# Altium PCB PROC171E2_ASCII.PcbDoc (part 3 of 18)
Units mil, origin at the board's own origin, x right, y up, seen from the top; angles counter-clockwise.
Board outline 7700 x 2300 mil, 6 copper layers (Top Layer, GND 1, SIG 1, SIG 2, GND 2, Bottom Layer), stack 61.062 mil thick; 938 components, 688 nets, 11933 pads, 1723 vias.
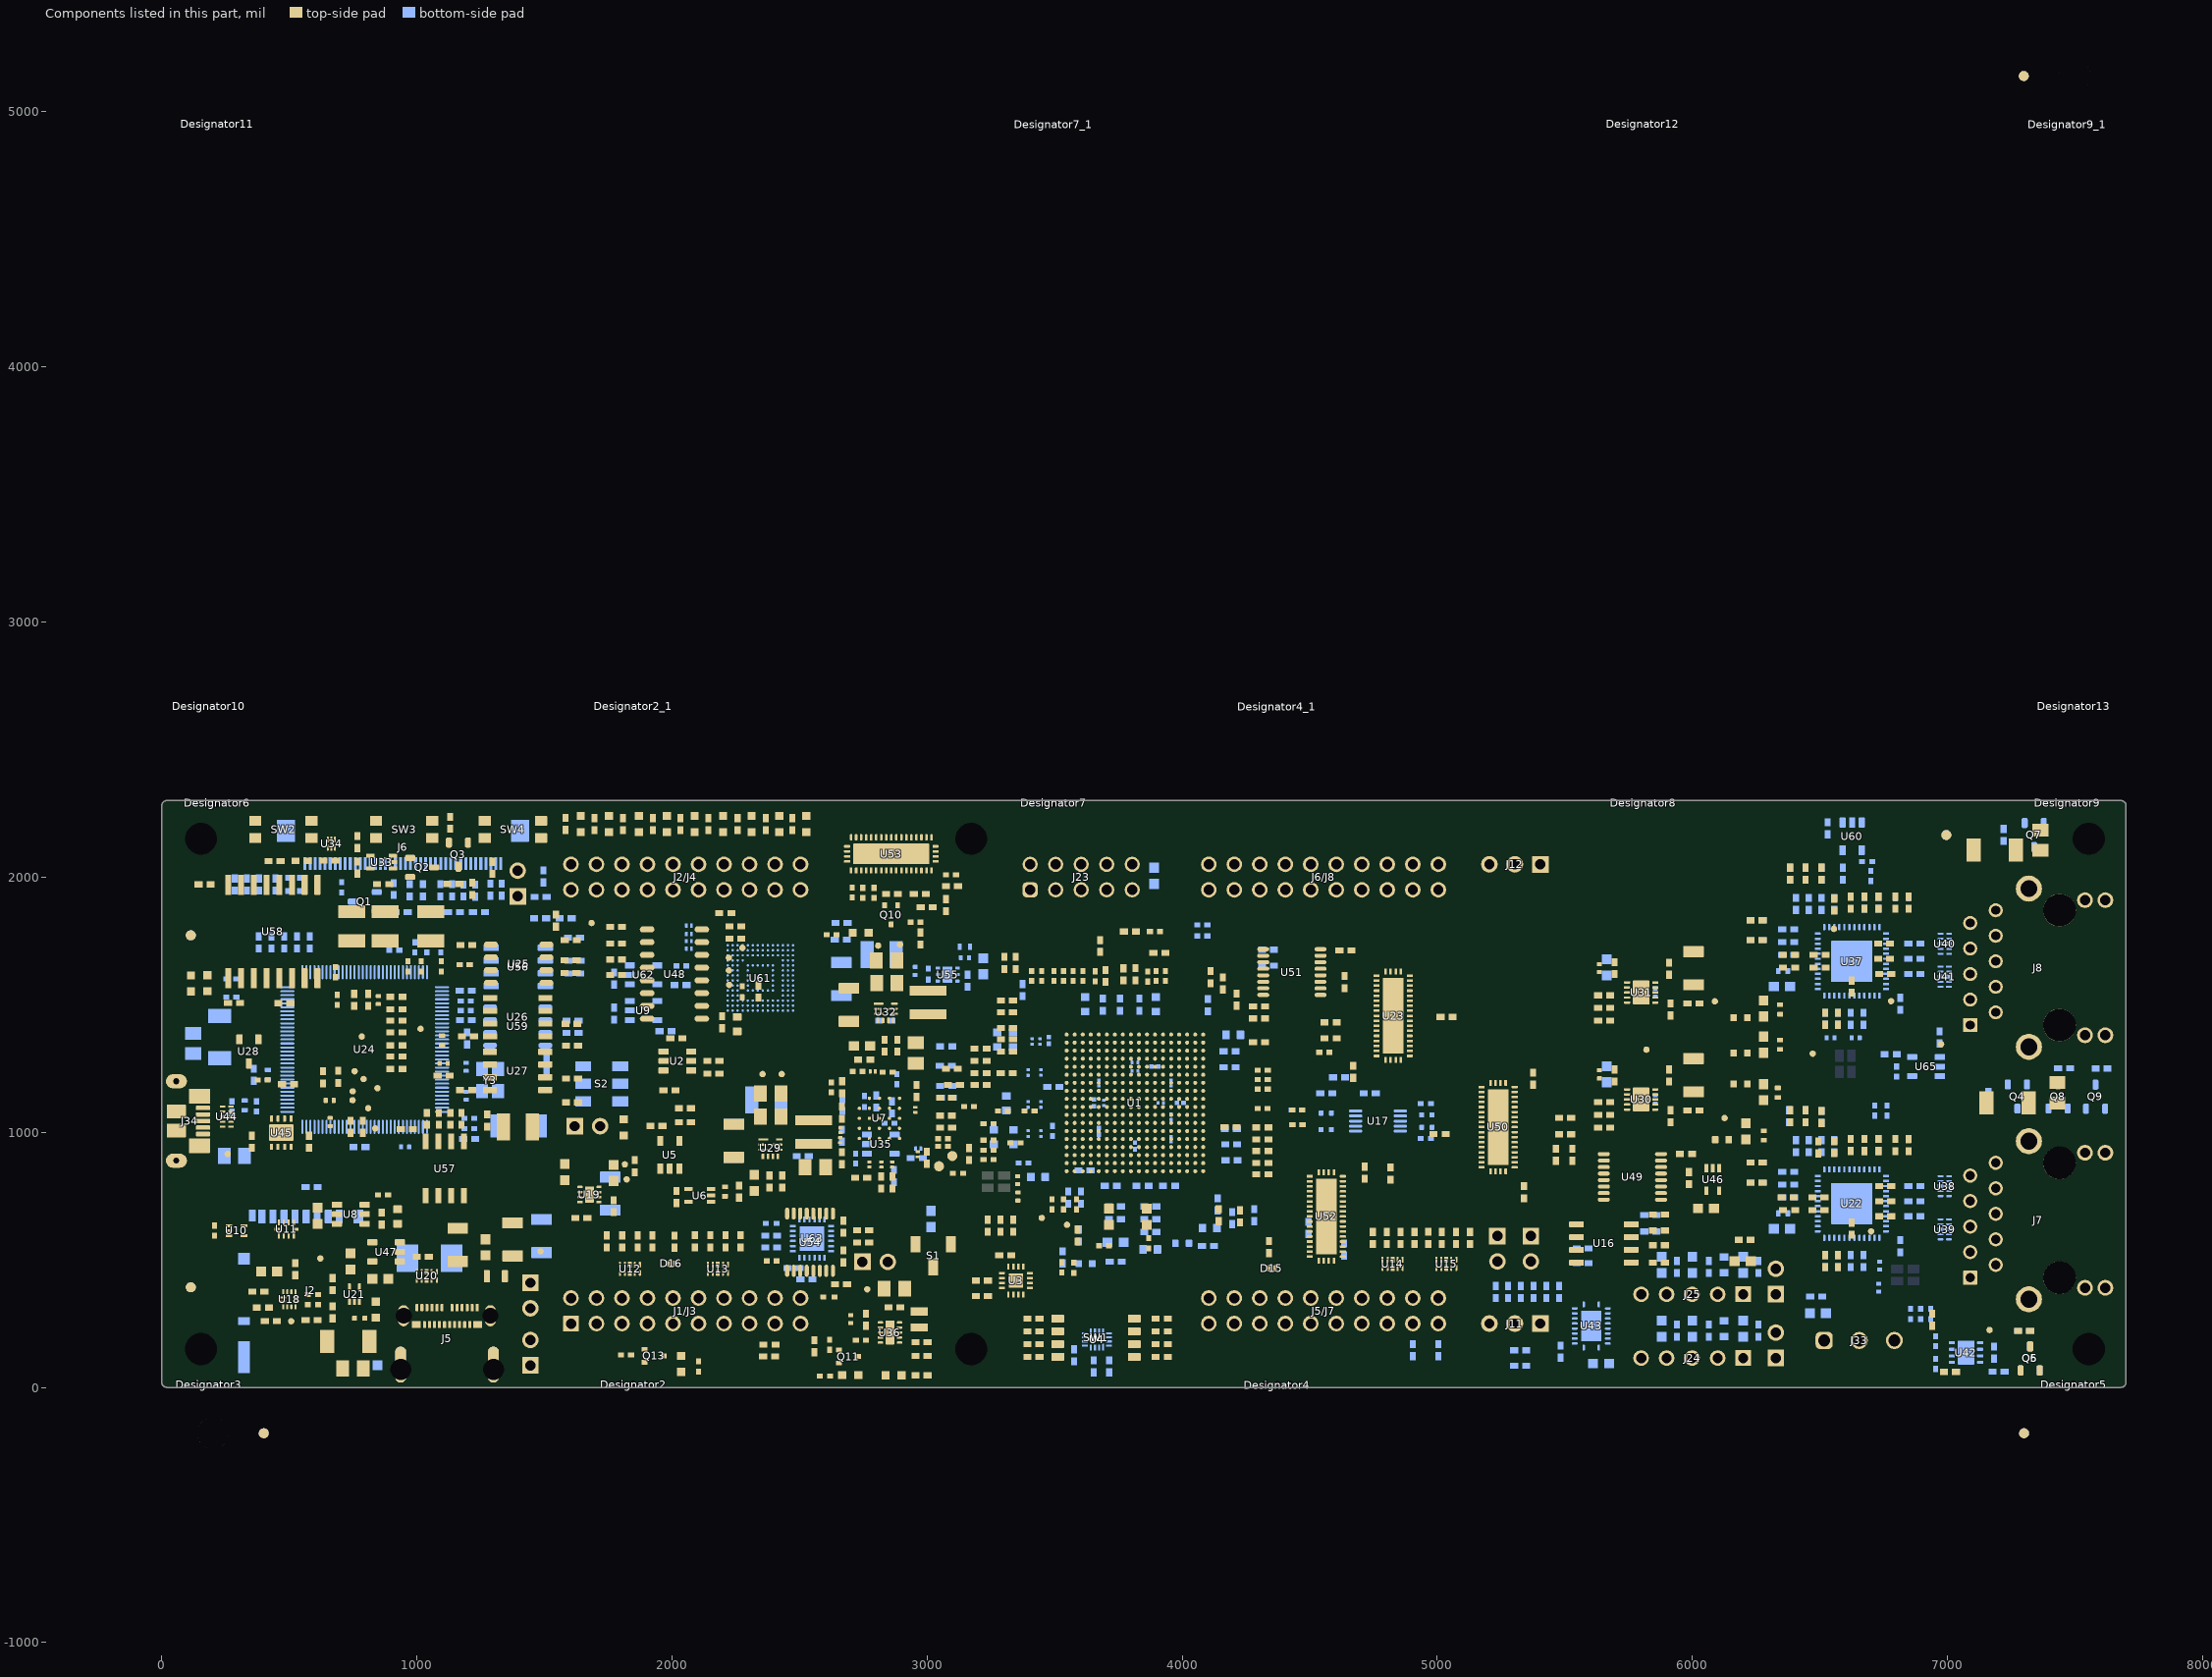
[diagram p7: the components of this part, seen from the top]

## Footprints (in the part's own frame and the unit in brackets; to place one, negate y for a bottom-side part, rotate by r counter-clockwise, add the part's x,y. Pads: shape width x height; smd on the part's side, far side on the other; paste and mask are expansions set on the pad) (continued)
BoosterPack_40pin_J1J3 [mm] "Receptacle, 2.54mm, 10x2, TH"
  rrect6% 1.55x1.55 hole 1.02: 1(1.27,11.43)
  round 1.55 hole 1.02: 2(1.27,8.89) 3(1.27,6.35) 4(1.27,3.81) 5(1.27,1.27) 6(1.27,-1.27) 7(1.27,-3.81) 8(1.27,-6.35) 9(1.27,-8.89) 10(1.27,-11.43) 21(-1.27,11.43) 22(-1.27,8.89) 23(-1.27,6.35) 24(-1.27,3.81) 25(-1.27,1.27) 26(-1.27,-1.27) 27(-1.27,-3.81) 28(-1.27,-6.35) 29(-1.27,-8.89) 30(-1.27,-11.43)
  silkscreen extent -7.62,-12.95 7.62,12.95
BoosterPack_40pin_J2J4 [mm] "Receptacle, 2.54mm, 10x2, TH"
  round 1.55 hole 1.02: 11(-1.27,-11.43) 12(-1.27,-8.89) 13(-1.27,-6.35) 14(-1.27,-3.81) 15(-1.27,-1.27) 16(-1.27,1.27) 17(-1.27,3.81) 18(-1.27,6.35) 19(-1.27,8.89) 20(-1.27,11.43) 31(1.27,-11.43) 32(1.27,-8.89) 33(1.27,-6.35) 34(1.27,-3.81) 35(1.27,-1.27) 36(1.27,1.27) 37(1.27,3.81) 38(1.27,6.35) 39(1.27,8.89) 40(1.27,11.43)
  silkscreen extent -7.62,-12.95 2.48,12.95
BoosterPack_40pin_J5J7 [mm] "Receptacle, 2.54mm, 10x2, TH"
  round 1.55 hole 1.02: 41(1.27,11.43) 42(1.27,8.89) 43(1.27,6.35) 44(1.27,3.81) 45(1.27,1.27) 46(1.27,-1.27) 47(1.27,-3.81) 48(1.27,-6.35) 49(1.27,-8.89) 50(1.27,-11.43) 61(-1.27,11.43) 62(-1.27,8.89) 63(-1.27,6.35) 64(-1.27,3.81) 65(-1.27,1.27) 66(-1.27,-1.27) 67(-1.27,-3.81) 68(-1.27,-6.35) 69(-1.27,-8.89) 70(-1.27,-11.43)
  silkscreen extent -2.48,-12.95 7.62,12.95
BoosterPack_40pin_J6J8 [mm] "Receptacle, 2.54mm, 10x2, TH"
  round 1.55 hole 1.02: 51(-1.27,-11.43) 52(-1.27,-8.89) 53(-1.27,-6.35) 54(-1.27,-3.81) 55(-1.27,-1.27) 56(-1.27,1.27) 57(-1.27,3.81) 58(-1.27,6.35) 59(-1.27,8.89) 60(-1.27,11.43) 71(1.27,-11.43) 72(1.27,-8.89) 73(1.27,-6.35) 74(1.27,-3.81) 75(1.27,-1.27) 76(1.27,1.27) 77(1.27,3.81) 78(1.27,6.35) 79(1.27,8.89) 80(1.27,11.43)
  silkscreen extent -7.62,-12.95 2.48,12.95
BRAKE_WAY_HOLES1X3 [mil]
  round 27 hole 32 unplated mask+0: ""(-50,49.37) ""(0,49.37) ""(50,49.37)
CE_Mark_5mm [mil] "Minimum text height for CE Mark"
D0008A-MFG [mm]
  rrect17% 1.55x0.6 smd paste+0 mask+0: 1(-2.7,1.905) 2(-2.7,0.635) 3(-2.7,-0.635) 4(-2.7,-1.905) 5(2.7,-1.905) 6(2.7,-0.635) 7(2.7,0.635) 8(2.7,1.905)
  silkscreen extent -4.17,-2.5 1.5,2.5
D0008B_HV [mm] "SOIC, 8-Leads, Body 4.9x3.9mm, Pitch 1.27mm, HV / Isolation option"
  rrect17% 1.4x0.6 smd: 1(-2.75,1.905) 2(-2.75,0.635) 3(-2.75,-0.635) 4(-2.75,-1.905) 5(2.75,-1.905) 6(2.75,-0.635) 7(2.75,0.635) 8(2.75,1.905)
  silkscreen extent -3.3,-2.5 0.9,2.5
D0008B_N [mil] "SOIC, 8-Leads, Body 4.9x3.9mm, Pitch 1.27mm, IPC Medium Density"
  oval 55x23.62 smd: 1(-108.5,75) 2(-108.5,25) 3(-108.5,-25) 4(-108.5,-75) 5(108.5,-75) 6(108.5,-25) 7(108.5,25) 8(108.5,75)
  silkscreen extent -130,-98 35,98
D0016A_N [mm] "SOIC, 16-Leads, Body 9.9x3.9mm, Pitch 1.27mm, IPC Medium Density"
  oval 1.45x0.6 smd: 1(-2.725,4.445) 2(-2.725,3.175) 3(-2.725,1.905) 4(-2.725,0.635) 5(-2.725,-0.635) 6(-2.725,-1.905) 7(-2.725,-3.175) 8(-2.725,-4.445) 9(2.725,-4.445) 10(2.725,-3.175) 11(2.725,-1.905) 12(2.725,-0.635) 13(2.725,0.635) 14(2.725,1.905) 15(2.725,3.175) 16(2.725,4.445)
  silkscreen extent -3.3,-5 0.9,5
DBV0005A_N [mm] "SOT23, 5-Leads, Body 2.9x1.6mm, Pitch 0.95mm, Lead Span 2.8mm, IPC Medium Density"
  rrect17% 1x0.6 smd: 1(-1.375,0.95) 2(-1.375,0) 3(-1.375,-0.95) 4(1.375,-0.95) 5(1.375,0.95)
  silkscreen extent -0.25,-1.55 0.25,1.55
DBV0006A_N [mm] "SOT23, 6-Leads, Body 2.9x1.6mm, Pitch 0.95mm, Lead Span 2.8mm, IPC Medium Density"
  rrect17% 1x0.6 smd: 1(-1.375,0.95) 2(-1.375,0) 3(-1.375,-0.95) 4(1.375,-0.95) 5(1.375,0) 6(1.375,0.95)
  silkscreen extent -1.68,-1.55 0.5,1.55
DBZ0003A_N [mm] "SOT23, 3-Leads, Body 2.9x1.3mm, Pitch 0.95mm, Lead Span 2.4mm, IPC Medium Density"
  rrect17% 1x0.6 smd: 1(-1.2,0.95) 2(-1.2,-0.95) 3(1.2,0)
  silkscreen extent 0.2,-1.5 0.7,1.5
DCK0005A_N [mm] "SOT353, 5-Leads, Body 2x1.3mm, Pitch 0.65mm, Lead Span 2.1mm, IPC Medium Density"
  rrect25% 0.85x0.4 smd: 1(-1.125,0.65) 2(-1.125,0) 3(-1.125,-0.65) 4(1.125,-0.65) 5(1.125,0.65)
  silkscreen extent -1.48,-1.02 0.55,1.1
DGS0010A_N [mm] "TSSOP, 10-Leads, Body 3x3mm, Pitch 0.5mm, IPC Medium Density"
  oval 1.35x0.3 smd: 1(-2.225,1) 2(-2.225,0.5) 3(-2.225,0) 4(-2.225,-0.5) 5(-2.225,-1) 6(2.225,-1) 7(2.225,-0.5) 8(2.225,0) 9(2.225,0.5) 10(2.225,1)
  silkscreen extent -2.75,-1.55 0.9,1.55
DPY0002A [mm] "X1SON-2"
  rrect57% 0.35x0.6 smd paste-0.5 mask+0: 1(-0.325,0) 2(0.325,0)
  rrect50% 0.3x0.5 on Top Paste: 1S(-0.35,0) 2S(0.35,0)
  silkscreen extent -0.85,-0.02 -0.8,0.02
DQA0010A#1 [mm] "SON, 10-Leads, Body 1x2.5mm, Pitch 0.5mm, TI Recommended"
  rrect50% 0.565x0.2 smd: 1(-0.417,1) 2(-0.417,0.5) 4(-0.417,-0.5) 5(-0.417,-1) 6(0.417,-1) 7(0.417,-0.5) 9(0.417,0.5) 10(0.417,1)
  rrect28% 0.565x0.36 on Top Paste: 3(-0.417,0) 8(0.417,0)
  rrect25% 0.565x0.4 smd paste-0.2: 3(-0.417,0) 8(0.417,0)
  silkscreen extent -0.67,-1.45 0.55,1.45
DQA0010A#2 [mm] "SON, 10-Leads, Body 1x2.5mm, Pitch 0.5mm, TI Recommended"
  rrect50% 0.565x0.2 smd: 1(-0.417,1) 2(-0.417,0.5) 4(-0.417,-0.5) 5(-0.417,-1) 6(0.417,-1) 7(0.417,-0.5) 9(0.417,0.5) 10(0.417,1)
  rrect28% 0.565x0.36 on Bottom Paste: 3(-0.417,0) 8(0.417,0)
  rrect25% 0.565x0.4 smd paste-0.2: 3(-0.417,0) 8(0.417,0)
  silkscreen extent -0.67,-1.45 0.55,1.45
DQC0010A [mm] "SON, 10-Leads, Body 2x3mm, Pitch 0.5mm, Thermal Pad 2.4x0.84mm"
  rrect40% 0.5x0.25 smd: 1(-0.95,1) 2(-0.95,0.5) 3(-0.95,0) 4(-0.95,-0.5) 5(-0.95,-1) 6(0.95,-1) 7(0.95,-0.5) 8(0.95,0) 9(0.95,0.5) 10(0.95,1)
  rrect12% 0.8x1.08 on Top Paste: 11(0,-0.64) 11(0,0.64)
  rrect12% 0.84x2.4 smd paste-0.42: 11(0,0)
  silkscreen extent -1.18,-1.68 1.17,1.68
DRB0008B [mm] "SON, 8-Leads, Body 3x3mm, Pitch 0.65mm, Thermal Pad 2.4x1.65mm, TI Recommended"
  rrect33% 0.6x0.3 smd: 1(-1.4,0.975) 2(-1.4,0.325) 3(-1.4,-0.325) 4(-1.4,-0.975) 5(1.4,-0.975) 6(1.4,-0.325) 7(1.4,0.325) 8(1.4,0.975)
  rrect50% 1.47x1.06 on Top Paste: 9(0,0.63) 9(0,-0.63)
  rrect6% 1.65x2.4 smd paste-1.2: 9(0,0)
  silkscreen extent -1.73,-1.73 1.73,1.73
DRB0008J [mm] "VSON-8"
  rrect33% 0.6x0.31 smd: 1(-1.4,0.975) 2(-1.4,0.325) 3(-1.4,-0.325) 4(-1.4,-0.975) 5(1.4,-0.975) 6(1.4,-0.325) 7(1.4,0.325) 8(1.4,0.975)
  rrect6% 1.65x2.4 smd paste-1.2: 9(0,0)
  silkscreen extent -1.73,-1.73 1.73,1.73
DRC0010J [mm] "VSON-10"
  rrect42% 0.6x0.24 smd: 1(-1.4,1) 2(-1.4,0.5) 3(-1.4,0) 4(-1.4,-0.5) 5(-1.4,-1) 6(1.4,-1) 7(1.4,-0.5) 8(1.4,0) 9(1.4,0.5) 10(1.4,1)
  rrect12% 1.65x2.4 smd paste-1 mask+0: 11(0,0)
DRL0005A [mm] "SOTFL, 5-Flat Leads, Body 1.2x1.6x0.6mm, Pitch 0.5mm, TI recommended"
  rrect33% 0.67x0.3 smd: 1(-0.74,0.5) 2(-0.74,0) 3(-0.74,-0.5) 4(0.74,-0.5) 5(0.74,0.5)
  silkscreen extent -0.9,-0.95 0.5,0.95
DRV0006A [mm] "SON, 6-Leads, Body 2x2mm, Pitch 0.65mm, Thermal Pad 1.6x1mm, TI Recommended"
  rrect33% 0.45x0.3 smd: 1(-0.975,0.65) 2(-0.975,0) 3(-0.975,-0.65) 4(0.975,-0.65) 5(0.975,0) 6(0.975,0.65)
  rrect14% 1x0.7 on Bottom Paste: 7(0,-0.45) 7(0,0.45)
  rrect10% 1x1.6 smd paste-0.5: 7(0,0)
  silkscreen extent -1.05,-1.2 1.05,1.2
DSF0006A [mm] "TI recommended land pattern"
  rrect59% 0.6x0.17 smd mask+0: 1(-0.4,0.35) 2(-0.4,0) 3(-0.4,-0.35) 4(0.4,-0.35) 5(0.4,0) 6(0.4,0.35)
  silkscreen extent -0.6,-0.63 0.6,0.63
DSG0008B [mm] "SON, 8-Leads, Body 2x2mm, Pitch 0.5mm, Thermal Pad 1.6x0.9mm, TI Recommended"
  rrect14% 0.9x0.7 on Top Paste: 0(0,-0.45) 0(0,0.45)
  rrect40% 0.5x0.25 smd: 1(-0.95,0.75) 2(-0.95,0.25) 3(-0.95,-0.25) 4(-0.95,-0.75) 5(0.95,-0.75) 6(0.95,-0.25) 7(0.95,0.25) 8(0.95,0.75)
  rrect11% 0.9x1.6 smd paste-0.45: 9(0,0)
  silkscreen extent -1.07,-1.15 1.07,1.15
DW0016A-MFG [mm]
  rrect17% 2x0.6 smd paste+0 mask+0: 1(-4.65,4.445) 2(-4.65,3.175) 3(-4.65,1.905) 4(-4.65,0.635) 5(-4.65,-0.635) 6(-4.65,-1.905) 7(-4.65,-3.175) 8(-4.65,-4.445) 9(4.65,-4.445) 10(4.65,-3.175) 11(4.65,-1.905) 12(4.65,-0.635) 13(4.65,0.635) 14(4.65,1.905) 15(4.65,3.175) 16(4.65,4.445)
  silkscreen extent -6.32,-5.25 3.15,5.25
FCC_disclaimer [mil]
Fiducial10-20 [mm]
  round 1 smd mask+0: 1(0,0)
  Top Layer keep-out circle w1.178: c0,0 r0.5
FP-2012670005_CONN_USB_9MM39_8MM21-MFG [mm]
  rrect100% 1.1x2.1 hole 1.6 slot 0.6 at 0 deg paste-1000 mask+0: 1(-4.32,3.205) 2(4.32,3.205)
  rrect100% 0.6x2.1 hole 2.1 slot 0.6 at 0 deg paste-1000 mask+0: 3(-4.62,-2.155) 4(4.62,-2.155)
  rrect100% 1.1x3.6 smd paste-1000 mask+0: 3(-4.62,-1.655) 4(4.62,-1.655)
  rrect100% 1.1x3.6 smd far side paste-1000 mask+0: 3(-4.62,-1.655) 4(4.62,-1.655)
  rrect33% 0.3x0.7 smd paste+0 mask+0: A1(-3,4.015) A2(-2.5,4.015) A3(-2,4.015) A4(-1.5,4.015) A5(-1,4.015) A6(-0.5,4.015) A7(0.5,4.015) A8(1,4.015) A9(1.5,4.015) A10(2,4.015) A11(2.5,4.015) A12(3,4.015) B2(2.25,2.315) B3(1.75,2.315) B4(1.25,2.315) B5(0.75,2.315) B6(0.25,2.315) B7(-0.25,2.315) B8(-0.75,2.315) B9(-1.25,2.315) B10(-1.75,2.315) B11(-2.25,2.315)
  rrect14% 0.9x0.7 smd paste+0 mask+0: B1(3.05,2.315) B12(-3.05,2.315)
  silkscreen extent -4.77,0.52 4.77,5.03
FP-74405020100_SMT_IND_2MM0_1MM6-MFG [mm]
  rect 0.8x1.7 smd paste+0 mask+0: 1(-0.8,0) 2(0.8,0)
FP-416131160804_SMT_SW-MFG [mm]
  rrect13% 0.76x1.27 smd paste+0 mask+0: 1(-1.905,-3.81) 2(-0.635,-3.81) 3(0.635,-3.81) 4(1.905,-3.81) 5(1.905,3.81) 6(0.635,3.81) 7(-0.635,3.81) 8(-1.905,3.81)
  silkscreen extent -3.27,-4.12 3.27,2.93
FP-434351045816_SMT_SW_4MM7_4MM5-MFG [mm]
  rrect10% 1.2x1 smd paste+0 mask+0: 1(2.8,0.85) 2(2.8,-0.85) 3(-2.8,0.85) 4(-2.8,-0.85)
  silkscreen extent -2.4,0.73 4.07,1.85
FP-BLM18EG121SN1D_0603-MFG [mm]
  rrect15% 0.65x0.7 smd paste+0 mask+0: 1(-0.675,0) 2(0.675,0)
  silkscreen extent -0.87,-0.8 0.87,0.8
FP-BLM21PG300SN1D_0805-MFG [mm]
  rrect17% 0.6x1.2 smd paste-1000 mask+0: 1(-0.9,0) 2(0.9,0)
  silkscreen extent -0.23,-0.72 0.23,0.72
FP-CL10A335KP8NNNC_0603-MFG [mm]
  rrect13% 0.76x0.85 smd paste+0 mask+0: 1(-0.72,0) 2(0.72,0)
  silkscreen extent -0.85,-0.8 0.85,0.8
"FP-CRCW020122R0FNED_0201 (0603 metric)-MFG" [mm]
  rrect36% 0.28x0.43 smd paste+0 mask+0: 1(-0.255,0) 2(0.255,0)
FP-ERA-2APB621X_0402-MFG [mm]
  rrect21% 0.475x0.5 smd paste+0 mask+0: 1(-0.512,0) 2(0.512,0)
  silkscreen extent -0.5,-0.63 0.5,0.63
FP-ERJ-2GEJ152X_0402-MFG [mm]
  rrect21% 0.475x0.5 smd paste+0 mask+0: 1(-0.512,0) 2(0.513,0)
  silkscreen extent -0.53,-0.63 0.53,0.63
FP-FH12A-40S-0.5SH(55)_FFC40-MFG [mm]
  rrect33% 0.3x1.3 smd paste-1000 mask+0: 1(9.75,-3.725) 2(9.25,-3.725) 3(8.75,-3.725) 4(8.25,-3.725) 5(7.75,-3.725) 6(7.25,-3.725) 7(6.75,-3.725) 8(6.25,-3.725) 9(5.75,-3.725) 10(5.25,-3.725) 11(4.75,-3.725) 12(4.25,-3.725) 13(3.75,-3.725) 14(3.25,-3.725) 15(2.75,-3.725) 16(2.25,-3.725) 17(1.75,-3.725) 18(1.25,-3.725) 19(0.75,-3.725) 20(0.25,-3.725) 21(-0.25,-3.725) 22(-0.75,-3.725) 23(-1.25,-3.725) 24(-1.75,-3.725) 25(-2.25,-3.725) 26(-2.75,-3.725) 27(-3.25,-3.725) 28(-3.75,-3.725) 29(-4.25,-3.725) 30(-4.75,-3.725) 31(-5.25,-3.725) 32(-5.75,-3.725) 33(-6.25,-3.725) 34(-6.75,-3.725) 35(-7.25,-3.725) 36(-7.75,-3.725) 37(-8.25,-3.725) 38(-8.75,-3.725) 39(-9.25,-3.725) 40(-9.75,-3.725)
  rrect6% 1.8x2.2 smd paste+0 mask+0: 41(-11.65,-0.475) 42(11.65,-0.475)
  silkscreen extent -12.35,-4.32 12.35,3.2
FP-GCM155R72A272KA37D_0402-MFG [mm]
  rrect25% 0.4x0.5 smd paste+0 mask+0: 1(-0.4,0) 2(0.4,0)
  silkscreen extent -0.53,-0.65 0.53,0.65
FP-GJM1555C1H8R0DB01D_0402-MFG [mm]
  rrect25% 0.4x0.5 smd paste+0 mask+0: 1(-0.4,0) 2(0.4,0)
  silkscreen extent -0.53,-0.63 0.53,0.63
FP-GJM1555C1H120JB01D_0402-MFG [mm]
  rrect25% 0.4x0.5 smd paste+0 mask+0: 1(-0.4,0) 2(0.4,0)
  silkscreen extent -0.53,-0.63 0.53,0.63
FP-GJM1555C1H150FB01D_0402-MFG [mm]
  rrect25% 0.4x0.5 smd paste+0 mask+0: 1(-0.4,0) 2(0.4,0)
  silkscreen extent -0.53,-0.63 0.53,0.63
FP-GQM1875C2E101JB12D_0603-MFG [mm]
  rrect13% 0.75x0.9 smd paste+0 mask+0: 1(-0.775,0) 2(0.775,0)
  silkscreen extent -1,-0.67 1,0.67
FP-GRM32EC72A106KE05L_1210-MFG [mm]
  rrect9% 1.1x2.05 smd paste+0 mask+0: 1(-1.65,0) 2(1.65,0)
  silkscreen extent -0.72,-1.35 0.72,1.35
FP-GRM033C80J105ME05D_0201-MFG [mm]
  rrect33% 0.3x0.35 smd paste+0 mask+0: 1(-0.282,0) 2(0.282,0)
  silkscreen extent -0.35,-0.58 0.35,0.58
FP-GRM155C71A105KE11D_0402-MFG [mm]
  rrect25% 0.4x0.5 smd paste+0 mask+0: 1(-0.4,0) 2(0.4,0)
  silkscreen extent -0.55,-0.65 0.55,0.65
FP-GRM155R71H104KE14D_0402-MFG [mm]
  rrect25% 0.4x0.5 smd paste+0 mask+0: 1(-0.4,0) 2(0.4,0)
  silkscreen extent -0.5,-0.65 0.5,0.65
FP-GRM1555C1E103JE01D_0402-MFG [mm]
  rrect22% 0.45x0.6 smd paste+0 mask+0: 1(-0.475,0) 2(0.475,0)
  silkscreen extent -0.58,-0.73 0.58,0.72
FP-IS25LX256-LHLE_TFBGA24-IPC_C [mm]
  round 0.34 smd paste+0 mask+0: A2(-1,2) A3(0,2) A4(1,2) A5(2,2) B1(-2,1) B2(-1,1) B3(0,1) B4(1,1) B5(2,1) C1(-2,0) C2(-1,0) C3(0,0) C4(1,0) C5(2,0) D1(-2,-1) D2(-1,-1) D3(0,-1) D4(1,-1) D5(2,-1) E1(-2,-2) E2(-1,-2) E3(0,-2) E4(1,-2) E5(2,-2)
  silkscreen extent -3.62,-4 3,4
FP-KGM05CR51A106MH_0402-MFG [mm]
  rrect20% 0.6x0.5 smd paste+0 mask+0: 1(-0.55,0) 2(0.55,0)
  silkscreen extent -0.6,-0.63 0.6,0.63
FP-LPJG16314A4NL_CONN_RJ45-MFG [mm]
  rrect7% 1.4x1.4 hole 0.9 paste-1000 mask+0: 1(-5.715,9.015)
  round 1.4 hole 0.9 paste-1000 mask+0: 2(-4.445,6.475) 3(-3.175,9.015) 4(-1.905,6.475) 5(-0.635,9.015) 6(0.635,6.475) 7(1.905,9.015) 8(3.175,6.475) 9(4.445,9.015) 10(5.715,6.475)
  round 1.57 hole 1.02 paste-1000 mask+0: 11(6.725,-2.415) 12(6.725,-4.445) 13(-6.725,-2.415) 14(-6.725,-4.445)
  round 2.6 hole 1.7 paste-1000 mask+0: 15(-7.875,3.175) 16(7.875,3.175)
  round 3.25 hole 3.25 unplated paste-1000 mask+0: ""(-5.715,0.125) ""(5.715,0.125)
  silkscreen extent -9.65,-10.75 8.1,10.75
FP-MTFC8GAMALBH-AAT_TFBGA153-MFG [mm]
  round 0.24 smd paste+0 mask+0: A1(-3.25,3.25) A2(-2.75,3.25) A3(-2.25,3.25) A4(-1.75,3.25) A5(-1.25,3.25) A6(-0.75,3.25) A7(-0.25,3.25) A8(0.25,3.25) A9(0.75,3.25) A10(1.25,3.25) A11(1.75,3.25) A12(2.25,3.25) A13(2.75,3.25) A14(3.25,3.25) B1(-3.25,2.75) B2(-2.75,2.75) B3(-2.25,2.75) B4(-1.75,2.75) B5(-1.25,2.75) B6(-0.75,2.75) B7(-0.25,2.75) B8(0.25,2.75) B9(0.75,2.75) B10(1.25,2.75) B11(1.75,2.75) B12(2.25,2.75) B13(2.75,2.75) B14(3.25,2.75) C1(-3.25,2.25) C2(-2.75,2.25) C3(-2.25,2.25) C4(-1.75,2.25) C5(-1.25,2.25) C6(-0.75,2.25) C7(-0.25,2.25) C8(0.25,2.25) C9(0.75,2.25) C10(1.25,2.25) C11(1.75,2.25) C12(2.25,2.25) C13(2.75,2.25) C14(3.25,2.25) D1(-3.25,1.75) D2(-2.75,1.75) D3(-2.25,1.75) D4(-1.75,1.75) D12(2.25,1.75) D13(2.75,1.75) D14(3.25,1.75) E1(-3.25,1.25) E2(-2.75,1.25) E3(-2.25,1.25) E5(-1.25,1.25) E6(-0.75,1.25) E7(-0.25,1.25) E8(0.25,1.25) E9(0.75,1.25) E10(1.25,1.25) E12(2.25,1.25) E13(2.75,1.25) E14(3.25,1.25) F1(-3.25,0.75) F2(-2.75,0.75) F3(-2.25,0.75) F5(-1.25,0.75) F10(1.25,0.75) F12(2.25,0.75) F13(2.75,0.75) F14(3.25,0.75) G1(-3.25,0.25) G2(-2.75,0.25) G3(-2.25,0.25) G5(-1.25,0.25) G10(1.25,0.25) G12(2.25,0.25) G13(2.75,0.25) G14(3.25,0.25) H1(-3.25,-0.25) H2(-2.75,-0.25) H3(-2.25,-0.25) H5(-1.25,-0.25) H10(1.25,-0.25) H12(2.25,-0.25) H13(2.75,-0.25) H14(3.25,-0.25) J1(-3.25,-0.75) J2(-2.75,-0.75) J3(-2.25,-0.75) J5(-1.25,-0.75) J10(1.25,-0.75) J12(2.25,-0.75) J13(2.75,-0.75) J14(3.25,-0.75) K1(-3.25,-1.25) K2(-2.75,-1.25) K3(-2.25,-1.25) K5(-1.25,-1.25) K6(-0.75,-1.25) K7(-0.25,-1.25) K8(0.25,-1.25) K9(0.75,-1.25) K10(1.25,-1.25) K12(2.25,-1.25) K13(2.75,-1.25) K14(3.25,-1.25) L1(-3.25,-1.75) L2(-2.75,-1.75) L3(-2.25,-1.75) L12(2.25,-1.75) L13(2.75,-1.75) L14(3.25,-1.75) M1(-3.25,-2.25) M2(-2.75,-2.25) M3(-2.25,-2.25) M4(-1.75,-2.25) M5(-1.25,-2.25) M6(-0.75,-2.25) M7(-0.25,-2.25) M8(0.25,-2.25) M9(0.75,-2.25) M10(1.25,-2.25) M11(1.75,-2.25) M12(2.25,-2.25) M13(2.75,-2.25) M14(3.25,-2.25) N1(-3.25,-2.75) N2(-2.75,-2.75) N3(-2.25,-2.75) N4(-1.75,-2.75) N5(-1.25,-2.75) N6(-0.75,-2.75) N7(-0.25,-2.75) N8(0.25,-2.75) N9(0.75,-2.75) N10(1.25,-2.75) N11(1.75,-2.75) N12(2.25,-2.75) N13(2.75,-2.75) N14(3.25,-2.75) P1(-3.25,-3.25) P2(-2.75,-3.25) P3(-2.25,-3.25) P4(-1.75,-3.25) P5(-1.25,-3.25) P6(-0.75,-3.25) P7(-0.25,-3.25) P8(0.25,-3.25) P9(0.75,-3.25) P10(1.25,-3.25) P11(1.75,-3.25) P12(2.25,-3.25) P13(2.75,-3.25) P14(3.25,-3.25)
  silkscreen extent -6.42,-6.55 5.8,6.55
Hirose_DM3BT-DSF-PEJS [mm] "Conncetor, micro SD, 8+2 Pos, R/A, SMT"
  rrect14% 0.7x1.4 smd: 1(-3.2,7.8) 2(-2.1,7.8) 3(-1,7.8) 4(0.1,7.8) 5(1.2,7.8) 6(2.3,7.8) 7(3.4,7.8) 8(4.5,7.8)
  rrect8% 1.2x0.8 smd: 9(6.3,-2.6)
  rrect14% 0.7x1.2 smd: 10(5.45,7.9)
  rrect10% 1x1.4 smd: S1(-5.1,7.8)
  rrect8% 1.2x1.2 smd: S2(6.3,3.6)
  rrect8% 1.2x3.2 smd: S3(6.3,-6.2)
  rrect8% 1x1 smd: S4(-7,-7)
Label_650x200 [mil] "Thermal Transfer Label"
  round 1 on Mech13: 0(0,0)
  silkscreen extent -325,-100 325,100
MHNP_M3_PANHEAD_PHILLIPS [mil]
  round 121 hole 126 unplated mask+0: ""(0,0)
  Keep-Out Layer circle w1: c0,0 r126
MISTRAL_LOGO_25 [mil]
  silkscreen extent 0,0 297,162
Molex_1051640001 [mm] "Receptacle, USB 2.0, Micro B, 5 Pos, 0.65mm Pitch, R/A, SMT"
  rrect22% 0.45x1.38 smd: 1(1.3,4.11) 2(0.65,4.11) 3(0,4.11) 4(-0.65,4.11) 5(-1.3,4.11)
  rrect7% 1.475x2.1 smd: 6(-2.462,3.75) 11(2.462,3.75)
  rrect100% 1.4x2.1 hole 0.6 slot 1.3 at 90 deg: 7(-3.95,1.45) 10(3.95,1.45)
  rrect7% 1.375x1.9 smd: 8(-0.937,1.45) 9(0.937,1.45)
  silkscreen extent 1.2,5.1 1.4,5.4
NDK_NX3225GA [mm] "NDK"
  rect 1.2x1.4 smd: 1(-0.8,1.1) 2(-0.8,-1.1) 3(0.8,-1.1) 4(0.8,1.1)
  silkscreen extent -1.9,-0.1 1.4,2
On-Shore_OSTTE030161 [mm] "Terminal Block, 3.5mm, 3x1, TH"
  rrect50% 1.7x1.7 hole 1.2: 1(-3.5,0)
  round 1.7 hole 1.2: 2(0,0) 3(3.5,0)
  silkscreen extent -5.25,-3.6 5.25,4.05
PBC03SAAN [mm] "Sullins 100mil, 1x3, 230 mil above insulator"
  rect 1.65x1.65 hole 1.016: 1(-2.54,0)
  round 1.65 hole 1.016: 2(0,0) 3(2.54,0)
  silkscreen extent -3.81,-1.27 3.81,1.27
PDT0128A [mm] "Thin QFP, 128-Leads, Body 14x14mm, Pitch 0.4mm"
  oval 1.4x0.2 smd: 1(-7.7,6.2) 2(-7.7,5.8) 3(-7.7,5.4) 4(-7.7,5) 5(-7.7,4.6) 6(-7.7,4.2) 7(-7.7,3.8) 8(-7.7,3.4) 9(-7.7,3) 10(-7.7,2.6) 11(-7.7,2.2) 12(-7.7,1.8) 13(-7.7,1.4) 14(-7.7,1) 15(-7.7,0.6) 16(-7.7,0.2) 17(-7.7,-0.2) 18(-7.7,-0.6) 19(-7.7,-1) 20(-7.7,-1.4) 21(-7.7,-1.8) 22(-7.7,-2.2) 23(-7.7,-2.6) 24(-7.7,-3) 25(-7.7,-3.4) 26(-7.7,-3.8) 27(-7.7,-4.2) 28(-7.7,-4.6) 29(-7.7,-5) 30(-7.7,-5.4) 31(-7.7,-5.8) 32(-7.7,-6.2) 65(7.7,-6.2) 66(7.7,-5.8) 67(7.7,-5.4) 68(7.7,-5) 69(7.7,-4.6) 70(7.7,-4.2) 71(7.7,-3.8) 72(7.7,-3.4) 73(7.7,-3) 74(7.7,-2.6) 75(7.7,-2.2) 76(7.7,-1.8) 77(7.7,-1.4) 78(7.7,-1) 79(7.7,-0.6) 80(7.7,-0.2) 81(7.7,0.2) 82(7.7,0.6) 83(7.7,1) 84(7.7,1.4) 85(7.7,1.8) 86(7.7,2.2) 87(7.7,2.6) 88(7.7,3) 89(7.7,3.4) 90(7.7,3.8) 91(7.7,4.2) 92(7.7,4.6) 93(7.7,5) 94(7.7,5.4) 95(7.7,5.8) 96(7.7,6.2)
  oval 0.2x1.4 smd: 33(-6.2,-7.7) 34(-5.8,-7.7) 35(-5.4,-7.7) 36(-5,-7.7) 37(-4.6,-7.7) 38(-4.2,-7.7) 39(-3.8,-7.7) 40(-3.4,-7.7) 41(-3,-7.7) 42(-2.6,-7.7) 43(-2.2,-7.7) 44(-1.8,-7.7) 45(-1.4,-7.7) 46(-1,-7.7) 47(-0.6,-7.7) 48(-0.2,-7.7) 49(0.2,-7.7) 50(0.6,-7.7) 51(1,-7.7) 52(1.4,-7.7) 53(1.8,-7.7) 54(2.2,-7.7) 55(2.6,-7.7) 56(3,-7.7) 57(3.4,-7.7) 58(3.8,-7.7) 59(4.2,-7.7) 60(4.6,-7.7) 61(5,-7.7) 62(5.4,-7.7) 63(5.8,-7.7) 64(6.2,-7.7) 97(6.2,7.7) 98(5.8,7.7) 99(5.4,7.7) 100(5,7.7) 101(4.6,7.7) 102(4.2,7.7) 103(3.8,7.7) 104(3.4,7.7) 105(3,7.7) 106(2.6,7.7) 107(2.2,7.7) 108(1.8,7.7) 109(1.4,7.7) 110(1,7.7) 111(0.6,7.7) 112(0.2,7.7) 113(-0.2,7.7) 114(-0.6,7.7) 115(-1,7.7) 116(-1.4,7.7) 117(-1.8,7.7) 118(-2.2,7.7) 119(-2.6,7.7) 120(-3,7.7) 121(-3.4,7.7) 122(-3.8,7.7) 123(-4.2,7.7) 124(-4.6,7.7) 125(-5,7.7) 126(-5.4,7.7) 127(-5.8,7.7) 128(-6.2,7.7)
  silkscreen extent -7.7,-6.3 6.3,6.99
PW0016A_L [mm] "TSOP, 16-Leads, Body 5x4.4mm, Pitch 0.65mm, IPC High Density"
  oval 1.2x0.4 smd: 1(-2.85,2.275) 2(-2.85,1.625) 3(-2.85,0.975) 4(-2.85,0.325) 5(-2.85,-0.325) 6(-2.85,-0.975) 7(-2.85,-1.625) 8(-2.85,-2.275) 9(2.85,-2.275) 10(2.85,-1.625) 11(2.85,-0.975) 12(2.85,-0.325) 13(2.85,0.325) 14(2.85,0.975) 15(2.85,1.625) 16(2.85,2.275)
  silkscreen extent -2,-2.55 1.85,2.55
RGT0016A [mm] "QFN, 16-Leads, Body 3x3mm, Pitch 0.5mm, Thermal Pad 1.45x1.45mm, TI Recommended"
  rrect42% 0.6x0.24 smd: 1(-1.4,0.75) 2(-1.4,0.25) 3(-1.4,-0.25) 4(-1.4,-0.75) 9(1.4,-0.75) 10(1.4,-0.25) 11(1.4,0.25) 12(1.4,0.75)
  rrect42% 0.24x0.6 smd: 5(-0.75,-1.4) 6(-0.25,-1.4) 7(0.25,-1.4) 8(0.75,-1.4) 13(0.75,1.4) 14(0.25,1.4) 15(-0.25,1.4) 16(-0.75,1.4)
  rrect7% 1.34x1.34 on Top Paste: 17(0,0)
  rrect7% 1.45x1.45 smd paste-0.725: 17(0,0)
  silkscreen extent -1.72,-1.73 1.72,1.73
RGY0020A [mm] "QFN, 20-Leads, Body 4.5x3.5mm, Pitch 0.5mm, Thermal Pad 3.05x2.05mm, TI Recommended"
  oval 0.24x0.6 smd: 1(-0.75,2.15) 10(-0.75,-2.15) 11(0.75,-2.15) 20(0.75,2.15)
  oval 0.6x0.24 smd: 2(-1.65,1.75) 3(-1.65,1.25) 4(-1.65,0.75) 5(-1.65,0.25) 6(-1.65,-0.25) 7(-1.65,-0.75) 8(-1.65,-1.25) 9(-1.65,-1.75) 12(1.65,-1.75) 13(1.65,-1.25) 14(1.65,-0.75) 15(1.65,-0.25) 16(1.65,0.25) 17(1.65,0.75) 18(1.65,1.25) 19(1.65,1.75)
  rect 2.05x3.05 smd paste-1.025: 21(0,0)
  silkscreen extent -1.97,-2.47 1.97,2.48
RGZ0048B-MFG [mm]
  rrect42% 0.6x0.24 smd paste+0 mask+0: 1(-3.4,2.75) 2(-3.4,2.25) 3(-3.4,1.75) 4(-3.4,1.25) 5(-3.4,0.75) 6(-3.4,0.25) 7(-3.4,-0.25) 8(-3.4,-0.75) 9(-3.4,-1.25) 10(-3.4,-1.75) 11(-3.4,-2.25) 12(-3.4,-2.75) 25(3.4,-2.75) 26(3.4,-2.25) 27(3.4,-1.75) 28(3.4,-1.25) 29(3.4,-0.75) 30(3.4,-0.25) 31(3.4,0.25) 32(3.4,0.75) 33(3.4,1.25) 34(3.4,1.75) 35(3.4,2.25) 36(3.4,2.75)
  rrect42% 0.24x0.6 smd paste+0 mask+0: 13(-2.75,-3.4) 14(-2.25,-3.4) 15(-1.75,-3.4) 16(-1.25,-3.4) 17(-0.75,-3.4) 18(-0.25,-3.4) 19(0.25,-3.4) 20(0.75,-3.4) 21(1.25,-3.4) 22(1.75,-3.4) 23(2.25,-3.4) 24(2.75,-3.4) 37(2.75,3.4) 38(2.25,3.4) 39(1.75,3.4) 40(1.25,3.4) 41(0.75,3.4) 42(0.25,3.4) 43(-0.25,3.4) 44(-0.75,3.4) 45(-1.25,3.4) 46(-1.75,3.4) 47(-2.25,3.4) 48(-2.75,3.4)
  rrect2% 4.1x4.1 smd paste-1000 mask+0: 49(0,0)
  silkscreen extent -4.38,-3.57 3.57,3.57
RPU0010A-MFG [mm]
  rrect50% 0.65x0.2 smd paste+0 mask+0: 1(-0.875,0.25) 3(-0.875,-0.75) 5(0.875,-0.25)
  rrect50% 1x0.2 smd paste+0 mask+0: 2(-0.7,-0.25) 4(0.7,-0.75) 6(0.7,0.25)
  rrect40% 0.25x0.55 smd paste+0 mask+0: 7(0.75,0.925) 8(0.25,0.925) 9(-0.25,0.925) 10(-0.75,0.925)
  silkscreen extent -1.97,-1.5 1,1.6
RSE0010A [mm] "QFN, 10-Leads, Body 1.5x2mm, Pitch 0.5mm, TI Recommended"
  rect 0.55x0.2 smd: 1(-0.675,0.75) 2(-0.675,0.25) 3(-0.675,-0.25) 4(-0.675,-0.75) 6(0.675,-0.75) 7(0.675,-0.25) 8(0.675,0.25) 9(0.675,0.75)
  rect 0.3x0.6 smd: 5(0,-0.9) 10(0,0.9)
  silkscreen extent -1.07,-1.17 0.77,1.18
RSV0016A [mm] "QFN, 16-Leads, Body 1.8x2.6mm, Pitch 0.4mm, TI Recommended"
  rect 0.7x0.2 smd: 1(-0.75,0.6)
  rect 0.6x0.2 smd: 2(-0.8,0.2) 3(-0.8,-0.2) 4(-0.8,-0.6) 9(0.8,-0.6) 10(0.8,-0.2) 11(0.8,0.2) 12(0.8,0.6)
  rect 0.2x0.6 smd: 5(-0.6,-1.2) 6(-0.2,-1.2) 7(0.2,-1.2) 8(0.6,-1.2) 13(0.6,1.2) 14(0.2,1.2) 15(-0.2,1.2) 16(-0.6,1.2)
  silkscreen extent -1.08,-1.33 1.08,1.45
RTW0024B [mm] "QFN, 24-Leads, Body 4x4mm, Pitch 0.5mm, Thermal Pad 2.45x2.45mm, TI Recommended"
  rrect42% 0.6x0.24 smd: 1(-1.9,1.25) 2(-1.9,0.75) 3(-1.9,0.25) 4(-1.9,-0.25) 5(-1.9,-0.75) 6(-1.9,-1.25) 13(1.9,-1.25) 14(1.9,-0.75) 15(1.9,-0.25) 16(1.9,0.25) 17(1.9,0.75) 18(1.9,1.25)
  rrect42% 0.24x0.6 smd: 7(-1.25,-1.9) 8(-0.75,-1.9) 9(-0.25,-1.9) 10(0.25,-1.9) 11(0.75,-1.9) 12(1.25,-1.9) 19(1.25,1.9) 20(0.75,1.9) 21(0.25,1.9) 22(-0.25,1.9) 23(-0.75,1.9) 24(-1.25,1.9)
  rrect4% 2.45x2.45 smd paste-1.225: 25(0,0)
  silkscreen extent -2.22,-2.22 2.22,2.22
RUA0042A-MFG [mm]
  rrect40% 0.6x0.25 smd paste+0 mask+0: 1(-1.65,4) 2(-1.65,3.5) 3(-1.65,3) 4(-1.65,2.5) 5(-1.65,2) 6(-1.65,1.5) 7(-1.65,1) 8(-1.65,0.5) 9(-1.65,0) 10(-1.65,-0.5) 11(-1.65,-1) 12(-1.65,-1.5) 13(-1.65,-2) 14(-1.65,-2.5) 15(-1.65,-3) 16(-1.65,-3.5) 17(-1.65,-4) 22(1.65,-4) 23(1.65,-3.5) 24(1.65,-3) 25(1.65,-2.5) 26(1.65,-2) 27(1.65,-1.5) 28(1.65,-1) 29(1.65,-0.5) 30(1.65,0) 31(1.65,0.5) 32(1.65,1) 33(1.65,1.5) 34(1.65,2) 35(1.65,2.5) 36(1.65,3) 37(1.65,3.5) 38(1.65,4)
  rrect40% 0.25x0.6 smd paste+0 mask+0: 18(-0.75,-4.4) 19(-0.25,-4.4) 20(0.25,-4.4) 21(0.75,-4.4) 39(0.75,4.4) 40(0.25,4.4) 41(-0.25,4.4) 42(-0.75,4.4)
  rrect5% 2.05x7.55 smd paste-1000 mask+0: 43(0,0)
  silkscreen extent -2.65,-4.55 1.8,4.55
RWB0012A [mm] "QFN, 12-Leads, Body 1.6x1.6mm, Pitch 0.4mm"
  rrect57% 0.7x0.2 smd paste-0.1: 1(-0.65,0.2) 2(-0.65,-0.2) 7(0.65,-0.2) 8(0.65,0.2)
  rrect57% 0.2x0.5 smd: 3(-0.6,-0.75) 4(-0.2,-0.75) 5(0.2,-0.75) 6(0.6,-0.75) 9(0.6,0.75) 10(0.2,0.75) 11(-0.2,0.75) 12(-0.6,0.75)
  silkscreen extent -0.92,-0.91 0.92,0.91
SMB-Bi [mil] "Molded Diode, 2-Leads, Body 5.4x3.6mm, IPC Medium Density, based on OnSemi component dimensions"
  rect 85x107.99 smd: 1(-87.01,0) 2(87.01,0)
  silkscreen extent -125,-79 125,79
SOIC-8 [mm] "duplicate of SO-8.  SOIC, 8-Leads, Body 5.0x4.0mm (max), Pitch 1.27mm, IPC Medium Density"
  rrect17% 1.45x0.6 smd: 1(-2.725,1.905) 2(-2.725,0.635) 3(-2.725,-0.635) 4(-2.725,-1.905) 5(2.725,-1.905) 6(2.725,-0.635) 7(2.725,0.635) 8(2.725,1.905)
  silkscreen extent -3.5,-2.5 0.9,2.5
SOT-23 [mm] "SOT23, 3-Leads, Body 2.9x1.3mm, Pitch 0.95mm, Lead Span 2.5mm, IPC Medium Density"
  rrect50% 1x0.6 smd: 1(-1.2,0.95) 2(-1.2,-0.95) 3(1.2,0)
  silkscreen extent -1.63,-1.5 0.7,1.5
SOT-323 [mm] "Diodes Inc recommended land pattern.  2016-02-24"
  rrect21% 0.6x0.47 smd: 1(-0.95,0.65) 2(-0.95,-0.65) 3(0.95,0)
  silkscreen extent -1.14,-1.22 0.77,1.22
Sullins_PBC02SAAN [mm] "Sullins 100mil, 1x2, 230 mil above insulator"
  rect 1.65x1.65 hole 1.016: 1(0,1.27)
  round 1.65 hole 1.016: 2(0,-1.27)
  silkscreen extent -1.37,-2.54 1.27,3.1
Sullins_PxC05SAAN [mm] "Header, 2.54mm, 5x1, TH"
  rect 1.55x1.55 hole 1.016: 1(-5.08,0)
  round 1.55 hole 1.016: 2(-2.54,0) 3(0,0) 4(2.54,0) 5(5.08,0)
  silkscreen extent -6.35,-1.75 6.35,1.27
Sullins_xxPC005DAAN-RC [mm] "Header, 2.54mm, 5x2, TH"
  rrect50% 1.5x1.5 hole 1: 1(-1.27,5.08)
  round 1.5 hole 1: 2(1.27,5.08) 3(-1.27,2.54) 4(1.27,2.54) 5(-1.27,0) 6(1.27,0) 7(-1.27,-2.54) 8(1.27,-2.54) 9(-1.27,-5.08) 10(1.27,-5.08)
SW_CAS-120TA [mm] "COPAL ELECTRONICS"
  rect 1.6x1 smd: 1(-1.15,1.75) 2(1.15,0) 3(-1.15,-1.75)
  silkscreen extent -2,-2.85 1.4,2.93
SW_CAS-D20TA [mm] "SMD, 6-Leads, Body 5.4x3.9mm, Pitch 1.75mm"
  rect 1.6x1 smd: 1(-1.85,1.75) 2(-1.85,0) 3(-1.85,-1.75) 4(1.85,1.75) 5(1.85,0) 6(1.85,-1.75)
  silkscreen extent -1.95,-2.7 1.95,2.9
TI_Stacked_Overlay_Small [mil]
TP_25MIL-SMT [mil]
  round 25 smd mask+0: 1(0,0)
TP_SM_1MM [mm] "1mm Test Point, SMT"
  round 1 smd paste-0.5: 1(0,0)
WE-MAPI_4020 [mm] "SMD, 2-Leads, Body 4.1x4.1mm"
  rect 0.98x3.7 smd: 1(-1.185,0) 2(1.185,0)
  silkscreen extent -2.15,-2.15 2.15,2.15
WEEE_Minimum [mil] "WEEElie bin"
  silkscreen extent 22,-71 54,74
WL-SMCW_GREEN [mm] "WURTH"
  rect 0.8x0.8 smd: 1(-0.8,0) 2(0.8,0)
  silkscreen extent -1.9,-0.8 1.2,0.8
WL-SMCW_RED [mm] "WURTH"
  rect 0.8x0.8 smd: 1(-0.8,0) 2(0.8,0)
  silkscreen extent -1.9,-0.8 1.2,0.8
ZCZ0324A-MFG [mm]
  round 0.4 smd paste+0 mask+0: A1(-6.8,6.8) A2(-6,6.8) A3(-5.2,6.8) A4(-4.4,6.8) A5(-3.6,6.8) A6(-2.8,6.8) A7(-2,6.8) A8(-1.2,6.8) A9(-0.4,6.8) A10(0.4,6.8) A11(1.2,6.8) A12(2,6.8) A13(2.8,6.8) A14(3.6,6.8) A15(4.4,6.8) A16(5.2,6.8) A17(6,6.8) A18(6.8,6.8) B1(-6.8,6) B2(-6,6) B3(-5.2,6) B4(-4.4,6) B5(-3.6,6) B6(-2.8,6) B7(-2,6) B8(-1.2,6) B9(-0.4,6) B10(0.4,6) B11(1.2,6) B12(2,6) B13(2.8,6) B14(3.6,6) B15(4.4,6) B16(5.2,6) B17(6,6) B18(6.8,6) C1(-6.8,5.2) C2(-6,5.2) C3(-5.2,5.2) C4(-4.4,5.2) C5(-3.6,5.2) C6(-2.8,5.2) C7(-2,5.2) C8(-1.2,5.2) C9(-0.4,5.2) C10(0.4,5.2) C11(1.2,5.2) C12(2,5.2) C13(2.8,5.2) C14(3.6,5.2) C15(4.4,5.2) C16(5.2,5.2) C17(6,5.2) C18(6.8,5.2) D1(-6.8,4.4) D2(-6,4.4) D3(-5.2,4.4) D4(-4.4,4.4) D5(-3.6,4.4) D6(-2.8,4.4) D7(-2,4.4) D8(-1.2,4.4) D9(-0.4,4.4) D10(0.4,4.4) D11(1.2,4.4) D12(2,4.4) D13(2.8,4.4) D14(3.6,4.4) D15(4.4,4.4) D16(5.2,4.4) D17(6,4.4) D18(6.8,4.4) E1(-6.8,3.6) E2(-6,3.6) E3(-5.2,3.6) E4(-4.4,3.6) E5(-3.6,3.6) E6(-2.8,3.6) E7(-2,3.6) E8(-1.2,3.6) E9(-0.4,3.6) E10(0.4,3.6) E11(1.2,3.6) E12(2,3.6) E13(2.8,3.6) E14(3.6,3.6) E15(4.4,3.6) E16(5.2,3.6) E17(6,3.6) E18(6.8,3.6) F1(-6.8,2.8) F2(-6,2.8) F3(-5.2,2.8) F4(-4.4,2.8) F5(-3.6,2.8) F6(-2.8,2.8) F7(-2,2.8) F8(-1.2,2.8) F9(-0.4,2.8) F10(0.4,2.8) F11(1.2,2.8) F12(2,2.8) F13(2.8,2.8) F14(3.6,2.8) F15(4.4,2.8) F16(5.2,2.8) F17(6,2.8) F18(6.8,2.8) G1(-6.8,2) G2(-6,2) G3(-5.2,2) G4(-4.4,2) G5(-3.6,2) G6(-2.8,2) G7(-2,2) G8(-1.2,2) G9(-0.4,2) G10(0.4,2) G11(1.2,2) G12(2,2) G13(2.8,2) G14(3.6,2) G15(4.4,2) G16(5.2,2) G17(6,2) G18(6.8,2) H1(-6.8,1.2) H2(-6,1.2) H3(-5.2,1.2) H4(-4.4,1.2) H5(-3.6,1.2) H6(-2.8,1.2) H7(-2,1.2) H8(-1.2,1.2) H9(-0.4,1.2) H10(0.4,1.2) H11(1.2,1.2) H12(2,1.2) H13(2.8,1.2) H14(3.6,1.2) H15(4.4,1.2) H16(5.2,1.2) H17(6,1.2) H18(6.8,1.2) J1(-6.8,0.4) J2(-6,0.4) J3(-5.2,0.4) J4(-4.4,0.4) J5(-3.6,0.4) J6(-2.8,0.4) J7(-2,0.4) J8(-1.2,0.4) J9(-0.4,0.4) J10(0.4,0.4) J11(1.2,0.4) J12(2,0.4) J13(2.8,0.4) J14(3.6,0.4) J15(4.4,0.4) J16(5.2,0.4) J17(6,0.4) J18(6.8,0.4) K1(-6.8,-0.4) K2(-6,-0.4) K3(-5.2,-0.4) K4(-4.4,-0.4) K5(-3.6,-0.4) K6(-2.8,-0.4) K7(-2,-0.4) K8(-1.2,-0.4) K9(-0.4,-0.4) K10(0.4,-0.4) K11(1.2,-0.4) K12(2,-0.4) K13(2.8,-0.4) K14(3.6,-0.4) K15(4.4,-0.4) K16(5.2,-0.4) K17(6,-0.4) K18(6.8,-0.4) L1(-6.8,-1.2) L2(-6,-1.2) L3(-5.2,-1.2) L4(-4.4,-1.2) L5(-3.6,-1.2) L6(-2.8,-1.2) L7(-2,-1.2) L8(-1.2,-1.2) L9(-0.4,-1.2) L10(0.4,-1.2) L11(1.2,-1.2) L12(2,-1.2) L13(2.8,-1.2) L14(3.6,-1.2) L15(4.4,-1.2) L16(5.2,-1.2) L17(6,-1.2) L18(6.8,-1.2) M1(-6.8,-2) M2(-6,-2) M3(-5.2,-2) M4(-4.4,-2) M5(-3.6,-2) M6(-2.8,-2) M7(-2,-2) M8(-1.2,-2) M9(-0.4,-2) M10(0.4,-2) M11(1.2,-2) M12(2,-2) M13(2.8,-2) M14(3.6,-2) M15(4.4,-2) M16(5.2,-2) M17(6,-2) M18(6.8,-2) N1(-6.8,-2.8) N2(-6,-2.8) N3(-5.2,-2.8) N4(-4.4,-2.8) N5(-3.6,-2.8) N6(-2.8,-2.8) N7(-2,-2.8) N8(-1.2,-2.8) N9(-0.4,-2.8) N10(0.4,-2.8) N11(1.2,-2.8) N12(2,-2.8) N13(2.8,-2.8) N14(3.6,-2.8) N15(4.4,-2.8) N16(5.2,-2.8) N17(6,-2.8) N18(6.8,-2.8) P1(-6.8,-3.6) P2(-6,-3.6) P3(-5.2,-3.6) P4(-4.4,-3.6) P5(-3.6,-3.6) P6(-2.8,-3.6) P7(-2,-3.6) P8(-1.2,-3.6) P9(-0.4,-3.6) P10(0.4,-3.6) P11(1.2,-3.6) P12(2,-3.6) P13(2.8,-3.6) P14(3.6,-3.6) P15(4.4,-3.6) P16(5.2,-3.6) P17(6,-3.6) P18(6.8,-3.6) R1(-6.8,-4.4) R2(-6,-4.4) R3(-5.2,-4.4) R4(-4.4,-4.4) R5(-3.6,-4.4) R6(-2.8,-4.4) R7(-2,-4.4) R8(-1.2,-4.4) R9(-0.4,-4.4) R10(0.4,-4.4) R11(1.2,-4.4) R12(2,-4.4) R13(2.8,-4.4) R14(3.6,-4.4) R15(4.4,-4.4) R16(5.2,-4.4) R17(6,-4.4) R18(6.8,-4.4) T1(-6.8,-5.2) T2(-6,-5.2) T3(-5.2,-5.2) T4(-4.4,-5.2) T5(-3.6,-5.2) T6(-2.8,-5.2) T7(-2,-5.2) T8(-1.2,-5.2) T9(-0.4,-5.2) T10(0.4,-5.2) T11(1.2,-5.2) T12(2,-5.2) T13(2.8,-5.2) T14(3.6,-5.2) T15(4.4,-5.2) T16(5.2,-5.2) T17(6,-5.2) T18(6.8,-5.2) U1(-6.8,-6) U2(-6,-6) U3(-5.2,-6) U4(-4.4,-6) U5(-3.6,-6) U6(-2.8,-6) U7(-2,-6) U8(-1.2,-6) U9(-0.4,-6) U10(0.4,-6) U11(1.2,-6) U12(2,-6) U13(2.8,-6) U14(3.6,-6) U15(4.4,-6) U16(5.2,-6) U17(6,-6) U18(6.8,-6) V1(-6.8,-6.8) V2(-6,-6.8) V3(-5.2,-6.8) V4(-4.4,-6.8) V5(-3.6,-6.8) V6(-2.8,-6.8) V7(-2,-6.8) V8(-1.2,-6.8) V9(-0.4,-6.8) V10(0.4,-6.8) V11(1.2,-6.8) V12(2,-6.8) V13(2.8,-6.8) V14(3.6,-6.8) V15(4.4,-6.8) V16(5.2,-6.8) V17(6,-6.8) V18(6.8,-6.8)
  silkscreen extent -8.15,-7.55 7.55,7.55

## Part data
C1 C2 C3 C4 C5 C6 C14 C23 C25 C52 C53 C68 C236: library part CMP-0042976-1, "Cap Ceramic 3.3uF 10V X5R ±10% Pad SMD 0603 +85°C T/R"
C7 C8 C9 C10 C11 C12 C13 C15 C16 C17 C18 C24 C26 C27 C28 C34 C35 C36 C37 C38 C43 C48 C57 C60 C61 C62 C64 C65 C69 C70 C71 C78 C79 C80 C90 C91 C98 C99 C100 C111 C117 C119 C121 C125 C127 C131 C133 C134 C136 C137 C138 C139 C140 C141 C142 C145 C147 C150 C151 C154 C155 C163 C165 C174 C176 C181 C182 C183 C184 C186 C188 C194 C196 C198 C202 C204 C208 C210 C223 C225 C226 C233 C237 C238 C239 C240 C241 C242 C243 C244 C245 C246 C250 C251 C252 C257 C262: library part CMP-0006659-2, "CAP, CERM, 0.1 uF, 25 V, +/- 10%, X7R, 0402"
C19 C20 C21 C22 C29 C30 C31 C32 C39 C40 C41 C42 C44 C45 C46 C47: library part CMP-0093721-1, "Chip Multilayer Ceramic Capacitors for General Purpose, 0201, 1.0uF, X6S, 22%, 20%, 6.3V"
C33 C76 C77 C89: library part CMP-0007498-4, "CAP, CERM, 4.7 uF, 10 V, +/- 20%, X7R, 0603"
C49 C50 C51 C54 C55 C56: library part CMP-0064970-1, "CAP, CERM, 0.1 uF, 16 V,+/- 10%, X7R, 0201"
C58 C59 C112 C113 C189 C190: library part CMP-0035228-1, "Multi-Layer Ceramic Capacitor 12pF C0G  ±5% 0402 Paper T/R"
C63 C115 C123 C129 C135 C149 C152 C192 C200 C206: library part CMP-0035343-1, "Chip Multilayer Ceramic Capacitors for General Purpose, 0402, 10000pF, C0G, 30ppm/°C, 5%, 25V"
C66 C259 C260 C263 C264 C267 C268 C270 C271 C272: library part CMP-0006221-2, "CAP, CERM, 0.1 uF, 10 V, +/- 20%, X5R, 0402"
C67 C161 C172: library part CMP-0064936-4, "CAP, CERM, 4.7 uF, 16 V,+/- 10%, X7R, 0603"
C72 C73 C74 C75 C81 C82 C83 C84 C85 C86 C87 C88 C92 C93 C94 C95 C96 C97: library part CMP-0006456-2, "CAP, CERM, 330 pF, 50 V, +/- 5%, C0G/NP0, 0402"
C101 C106 C108 C110 C211 C212 C213 C224 C248 C249: library part CMP-0007469-4, "CAP, CERM, 0.1 uF, 100 V, +/- 10%, X7R, 0603"
C102 C104 C105 C107 C164 C167 C168 C175 C179 C180: library part CMP-0087970-1, "10µF ±10% 100V Ceramic Capacitor X7S 1210 (3225 Metric)"
C103: library part CMP-0007470-5, "CAP, CERM, 0.1 uF, 100 V, +/- 10%, X7R, 0603"
C109: library part CMP-0006412-2, "CAP, CERM, 1000 pF, 50 V, +/- 5%, C0G/NP0, 0402"
C114 C122 C128 C191 C199 C205: library part CMP-0007497-5, "CAP, CERM, 10 uF, 10 V, +/- 20%, X7R, 0603"
C116 C118 C120 C124 C126 C130 C132 C193 C195 C197 C201 C203 C207 C209: library part CMP-0006624-2, "CAP, CERM, 1 uF, 6.3 V, +/- 20%, X7R, 0402"
C143 C144: library part CMP-0035284-1, "Multi-Layer Ceramic Capacitor 8pF C0G  ±0.5pF 0402 Paper T/R"
C146 C148 C156 C162 C173 C187 C232: library part CMP-0035346-1, "1µF ±10% 10V Ceramic Capacitor X7S 0402 (1005 Metric)"
C153 C231: library part CMP-0006526-2, "CAP, CERM, 2.2 uF, 16 V, +/- 10%, X6S, 0402"
C157 C158 C169 C170 C185: library part CMP-0008377-2, "CAP, CERM, 22 uF, 10 V, +/- 20%, X7R, 0805"
C159 C171: library part CMP-0009221-2, "CAP, CERM, 47 uF, 10 V, +/- 20%, X7R, 1210"
C160 C177: library part CMP-0007424-4, "CAP, CERM, 0.47 uF, 25 V, +/- 10%, X7R, 0603"
C166 C178: library part CMP-0035196-1, "Ceramic Capacitor for Automotive 2.7nF ±10% 100VDC X7R 0402 Paper T/R"
C214 C216 C217 C219 C220 C221: library part CMP-0007173-4, "CAP, CERM, 1000 pF, 50 V, +/- 5%, C0G/NP0, 0603"
C215 C218: library part CMP-0035320-1, "Ceramic Capacitor 100pF ±5% 250VDC C0G 0603 Paper T/R"
C222: library part CMP-0006692-2, "CAP, CERM, 4700 pF, 50 V, +/- 10%, X7R, 0402"
C227: library part CMP-0008378-2, "CAP, CERM, 10 uF, 25 V, +/- 10%, X7R, 0805"
C228: library part CMP-0035231-1, "Multi-Layer Ceramic Capacitor 15pF C0G  ±1% 0402 Paper T/R"
C229 C230 C234 C235 C247: library part CMP-0009436-2, "CAP, CERM, 1000 pF, 2000 V, +/- 10%, X7R, 1808"
C253 C255: library part CMP-0096855-1, "Chip Multilayer Ceramic Capacitors for General Purpose, 0402, 0.10uF, X7R, 15%, 10%, 50V"
C254 C258 C261 C265 C269: library part CMP-0043010-1, "10 µF ±20% 10V Ceramic Capacitor X5R 0402 (1005 Metric)"
C256: library part CMP-0006610-2, "CAP, CERM, 2.2 uF, 25 V, +/- 10%, X5R, 0402"
C266: library part CMP-0006286-2, "CAP, CERM, 1 uF, 16 V, +/- 10%, X6S, 0402"
D1: library part CMP-0005599-2, "Diode, TVS, Bi, 6.5 V, SMB"
D2 D3 D4 D5 D6 D7 D8 D9 D10 D11 D12 D13 D14: library part CMP-0002894-2, "LED, Green, SMD"
D15 D16: library part CMP-0073602-3, "1-Channel ESD Protection Diode for USB Type-C and Thunderbolt 3, DPY0002A (X1SON-2)"
DS1 DS2 DS3 DS4: library part CMP-0002947-3, "LED, Red, SMD"
FB1 FB2 FB3 FB4 FB5 FB6: library part CMP-0089199-1, "120 Ohms @ 100MHz 1  Ferrite Bead 0603 (1608 Metric) 2A 40mOhm"
FID1 FID2 FID3 FID4 FID5 FID6 FID7 FID8 FID9 FID10 FID11 FID12: library part CMP-0077181-1, "Fiducial mark.  There is nothing to buy or mount."
J1 J9 J10 J13 J14 J15 J16 J17 J18: library part CMP-0054566-1, "Header, 100mil, 2x1, Gold, TH"
J1/J3: library part CMP-0003837-4, "Receptacle, 2.54mm, 10x2, Tin, TH"
J2: library part CMP-0080007-1, "Conncetor, micro SD, 8+2 Pos, R/A, SMT"
J2/J4: library part CMP-0078266-4, "Receptacle, 2.54mm, 10x2, Tin, TH"
J5: library part CMP-0093552-1, "USB-C (USB TYPE-C) USB 3.2 Gen 2 (USB 3.1 Gen 2, Superspeed + (USB 3.1)) Receptacle Connector 24 Position Surface Mount, Right Angle; Through Hole"
J5/J7: library part CMP-0081070-3, "Receptacle, 2.54mm, 10x2, Tin, TH"
J6: library part CMP-0093156-1
J6/J8: library part CMP-0081071-3, "Receptacle, 2.54mm, 10x2, Tin, TH"
J7 J8: library part CMP-0093483-1, "RJ45 Connector with 1000 Base-TX Inetgrated Magnetic"
J11 J12: library part CMP-0002334-1, "Header, 100mil, 3x1, Gold, TH"
J23: library part CMP-0080722-2, "Header, 2.54mm, 5x2, Gold, TH"
J24 J25: library part CMP-0054597-1, "Header, 2.54mm, 5x1, Tin, TH"
J33: library part CMP-0075352-1, "Terminal Block, 3.5mm, 3x1, Tin, R/A, TH"
J34: library part CMP-0055311-1, "Receptacle, USB 2.0, Micro B, 5 Position, R/A, SMT"
L1: library part CMP-0098084-1, "Chip Ferrite Bead, 0805, 30O @ 100MHz, 0.014O, , 4A"
L2 L3: library part CMP-0064169-1, "Inductor, Shielded, 2.2 uH, 4.7 A, 0.029 ohm, SMD"
L4: library part CMP-0078538-1, "10µH Semi-Shielded Wirewound Inductor 580mA 816 mOhm Max Nonstandard"
LBL1: library part CMP-0003625-1, "Thermal Transfer Printable Labels, 0.650\" W x 0.200\" H - 10,000 per roll"
Logo1: library part CMP-0074844-1
Logo2: library part CMP-0074838-1, "Texas Instrument Corporate Signature"
Logo3: library part CMP-0074847-1, "FCC_disclaimer"
Logo4: library part CMP-0074769-1
Q1 Q2 Q3: library part CMP-0078819-2, "MOSFET, P-CH, -12 V, -4.3 A, SOT-23"
Q4 Q5 Q6 Q7 Q8 Q9: library part CMP-0000947-2, "MOSFET, N-CH, 100 V, 0.17 A, SOT-23"
Q10: library part CMP-0000010-3, "MOSFET, P-CH, -20 V, -0.39 A, SOT-323"
Q11 Q13: library part CMP-0000948-2, "MOSFET, N-CH, 100 V, 0.17 A, SOT-323"
R1 R6 R8 R10 R11 R14 R15 R16 R17 R20 R42 R43 R92 R93 R98 R146 R147 R155 R156 R173 R174 R177 R178 R179 R181 R182 R183 R184 R185 R186 R187 R188 R194 R258 R268 R269 R270 R271 R274 R275 R276 R287 R288 R291 R292 R295 R296 R298 R299 R301 R305 R306 R316 R318 R319 R320 R321 R322 R323 R336 R337 R338 R339 R340 R341 R364 R389 R390 R395 R396 R417 R419 R420 R422 R423 R424 R426 R439: library part CMP-0026658-1, "RES, 10.0 k, 1%, 0.1 W, 0402"
R2: library part CMP-0026240-2, "RES, 2.67 k, 1%, 0.063 W, AEC-Q200 Grade 0, 0402"
R3 R4 R5 R7 R18 R26 R33 R34 R35 R36 R37 R38 R44 R45 R75 R76 R77 R78 R79 R80 R87 R88 R89 R90 R100 R101 R102 R103 R104 R105 R106 R117 R118 R119 R129 R130 R131 R149 R150 R157 R158 R165 R167 R168 R169 R170 R171 R172 R180 R189 R190 R193 R196 R197 R198 R199 R200 R201 R212 R213 R214 R225 R227 R229 R231 R233 R235 R245 R248 R286 R307 R342 R343 R344 R345 R346 R347 R348 R349 R350 R351 R352 R353 R354 R355 R356 R357 R358 R359 R360 R377 R378 R379 R380 R382 R394 R402 R403 R404 R405 R409 R411 R413 R414 R416 R427 R428: library part CMP-0026992-3, "RES, 0, 5%, 0.1 W, AEC-Q200 Grade 0, 0402"
R9 R12 R13 R46 R47 R48 R49 R50 R51 R52 R53 R54 R57 R58 R59 R60 R65 R66 R67 R68 R69 R70 R81 R82 R83 R84 R85 R86 R99 R164 R166 R249 R280 R281 R282 R283 R284 R285 R297 R393 R401 R433 R436: library part CMP-0026880-3, "RES, 22, 5%, 0.063 W, AEC-Q200 Grade 0, 0402"
R19: library part CMP-0026703-1, "RES, 49.9, 1%, 0.1 W, AEC-Q200 Grade 0, 0402"
R21 R22 R23 R24 R25 R96 R97 R256 R278 R289 R290 R293 R294 R300 R304 R391 R392 R397 R398 R437: library part CMP-0078193-1, "RES, 1.0 k, 5%, 0.1 W, AEC-Q200 Grade 0, 0402"
R27 R28 R29 R30 R361 R365 R366 R376 R381 R429 R430 R431 R432: library part CMP-0087090-2, "RES Thick Film SMD 22O 1% 1/20W 0201 200ppm/°C"
R31 R39 R40 R41 R143 R244 R250 R375 R383 R384 R385 R386 R387 R388 R418 R421 R425 R435: library part CMP-0025958-3, "RES, 10.0 k, 1%, 0.063 W, AEC-Q200 Grade 0, 0402"
R32 R253: library part CMP-0020616-3, "RES, 0, 5%, 0.125 W, AEC-Q200 Grade 0, 0805"
R55 R56 R95 R175 R176 R191 R192 R372 R399 R400 R407 R408: library part CMP-0026938-5, "RES, 4.7 k, 5%, 0.063 W, AEC-Q200 Grade 0, 0402"
R61 R62 R71 R72: library part CMP-0026696-1, "RES, 33.0, 1%, 0.1 W, 0402"
R63 R64 R73 R74: library part CMP-0042990-1, "Res Thick Film 0402 1.5K Ohm 5% 1/10W ±200ppm/°C Molded SMD Punched Carrier T/R"
R91: library part CMP-0026873-2, "RES, 200 k, 5%, 0.063 W, AEC-Q200 Grade 0, 0402"
R94: library part CMP-0026603-2, "RES, 909 k, 1%, 0.063 W, AEC-Q200 Grade 0, 0402"
R107 R202: library part CMP-0082348-1, "RES, 11.5 k, 1%, 0.1 W, AEC-Q200 Grade 0, 0402"
R108 R109 R110 R111 R112 R113 R114 R115 R116 R120 R121 R122 R123 R124 R125 R126 R127 R128 R153 R203 R204 R205 R206 R207 R208 R209 R210 R211 R215 R216 R217 R218 R219 R220 R221 R222 R223: library part CMP-0026237-2, "RES, 2.49 k, 1%, 0.063 W, AEC-Q200 Grade 0, 0402"
R132: library part CMP-0026993-2, "RES, 100, 5%, 0.1 W, AEC-Q200 Grade 0, 0402"
R133 R134 R135 R324 R325 R326 R327 R328 R329 R330 R331 R332 R333 R334 R335: library part CMP-0026299-2, "RES, 33.2, 1%, 0.063 W, AEC-Q200 Grade 0, 0402"
R136 R137: library part CMP-0078210-2, "RES, 330 k, 1%, 0.063 W, AEC-Q200 Grade 0, 0402"
R138 R139 R140 R141 R144 R261 R308 R309 R310 R311 R312: library part CMP-0026071-3, "RES, 1.00 k, 1%, 0.063 W, AEC-Q200 Grade 0, 0402"
R142: library part CMP-0026404-2, "RES, 49.9, 1%, 0.063 W, AEC-Q200 Grade 0, 0402"
R145: library part CMP-0026413-2, "RES, 4.87 k, 1%, 0.063 W, AEC-Q200 Grade 0, 0402"
R148 R160: library part CMP-0021602-3, "RES, 18.2 k, 1%, 0.125 W, AEC-Q200 Grade 0, 0805"
R151: library part CMP-0026336-2, "RES, 3.57 k, 1%, 0.063 W, AEC-Q200 Grade 0, 0402"
R152: library part CMP-0026093-3, "RES, 1.69 k, 1%, 0.063 W, AEC-Q200 Grade 0, 0402"
R154 R161 R163: library part CMP-0026414-2, "RES, 4.99 k, 1%, 0.063 W, AEC-Q200 Grade 0, 0402"
R159: library part CMP-0026097-2, "RES, 1.87 k, 1%, 0.063 W, AEC-Q200 Grade 0, 0402"
R162: library part CMP-0026028-3, "RES, 15.4 k, 1%, 0.063 W, AEC-Q200 Grade 0, 0402"
R195 R438: library part CMP-0026659-2, "RES, 100 k, 1%, 0.1 W, 0402"
R224 R226 R228 R230 R232 R234: library part CMP-0026878-3, "RES, 220, 5%, 0.063 W, AEC-Q200 Grade 0, 0402"
R236 R237 R238 R239 R240 R241 R242 R243 R367 R368 R369 R370 R371 R373 R374: library part CMP-0026702-1, "RES, 49.9 k, 1%, 0.1 W, AEC-Q200 Grade 0, 0402"
R246 R247: library part CMP-0026491-2, "RES, 61.9, 1%, 0.063 W, AEC-Q200 Grade 0, 0402"
R251: library part CMP-0026437-2, "RES, 51.1 k, 1%, 0.063 W, AEC-Q200 Grade 0, 0402"
R252: library part CMP-0078244-2, "RES, 30.0 k, 1%, 0.063 W, AEC-Q200 Grade 0, 0402"
R254 R255: library part CMP-0021522-3, "RES, 1.00 M, 1%, 0.125 W, AEC-Q200 Grade 0, 0805"
R257: library part CMP-0026704-1, "RES, 510, 1%, 0.1 W, 0402"
R259 R260 R265 R302 R314: library part CMP-0078194-1, "RES, 360, 5%, 0.1 W, AEC-Q200 Grade 0, 0402"
R262 R263 R264 R266 R267 R273 R277 R279: library part CMP-0026680-1, "RES, 220, 1%, 0.1 W, AEC-Q200 Grade 0, 0402"
R272 R303 R317: library part CMP-0078212-1, "RES, 510, 5%, 0.1 W, AEC-Q200 Grade 0, 0402"
R313 R315: library part CMP-0025998-3, "RES, 130, 1%, 0.063 W, AEC-Q200 Grade 0, 0402"
R362: library part CMP-0023078-5, "RES, 3.16 k, 1%, 0.1 W, 0603"
R363: library part CMP-0026088-3, "RES, 1.50 k, 1%, 0.063 W, AEC-Q200 Grade 0, 0402"
R406 R410 R412 R415: library part CMP-0015017-3, "RES, 0, 1%, 0.75 W, AEC-Q200 Grade 0, 1210"
R434: library part CMP-0093717-1, "620 Ohms ±0.1% 0.063W, 1/16W Chip Resistor 0402 (1005 Metric) Automotive AEC-Q200 Thin Film"
S1: library part CMP-0002139-2, "Switch, Slide, SPDT  100mA, SMT"
S2: library part CMP-0002233-1, "Switch, Dual SPDT,  2 Pos, 0.1A, 6VDC, SMD"
SW1: library part CMP-0093176-1, "Dip Switch SPST 4 Position Surface Mount Slide (Standard) Actuator 25mA 24VDC"
SW2 SW3 SW4: library part CMP-0093456-1, "Tactile Switch SPST-NO Side Actuated Surface Mount, Right Angle"
TP1 TP2: library part CMP-0003825-1, "1mm Test Point, SMT"
TP3 TP4 TP5 TP6 TP7 TP8 TP9 TP10 TP11 TP12 TP13 TP14 TP15 TP16 TP17 TP18 TP19 TP20 TP21 TP22 TP23 TP24 TP25 TP26 TP27 TP28 TP29 TP30 TP31 TP32 TP33 TP34 TP35 TP36 TP37 TP38: library part CMP-0078143-3, "TEST POINT.  No entry in BOM."
U1: library part CMP-0001698-2, "Sitara™ Microcontroller"
U2: library part CMP-0051219-1, "Single 3-Input Positive-AND Gate, DBV0006A, LARGE T&R"
U3: library part CMP-0043157-2, "Low-Voltage 8-Bit I2C and SMBus I/O Expander, 1.65 to 5.5 V, -40 to 85 degC, 16-pin QFN (RGT), Green (RoHS & no Sb/Br)"
U4: library part CMP-0066450-2, "4-Bit Dual-Supply Bus Transceiver with Configurable Voltage-Level Shifting and 3-State Outputs, RSV0016A (UQFN-16)"
U5 U9 U35 U47 U60 U62 U65: library part CMP-0051588-2, "Single 2-Input Positive-AND Gate, DBV0005A, LARGE T&R"
U6: library part CMP-0051704-3, "Single Schmitt-Trigger Buffer, DCK0005A, LARGE T&R"
U7: library part CMP-0120691-1, "FLASH Memory IC 256Mbit SPI - Octal I/O 133 MHz 6 ns 24-TFBGA (6x8)"
U8: library part CMP-0081995-1, "5.5V, 2A, 52mO Automotive High-Side Load Switch with Adjustable Rise Time & Quick Output Discharge, DBV0006A (SOT-23-6)"
U10: library part CMP-0043096-2, "Low-Capacitance + / - 15 kV ESD-Protection Array for High-Speed Data Interfaces, 2 Channels, -40 to +85 degC, 5-pin SOT (DRL), Green (RoHS & no Sb/Br)"
U11: library part CMP-0043123-1, "Low-Capacitance + / - 15 kV ESD Protection Array for High-Speed Data Interfaces, 6 Channels, -40 to +85 degC, 10-pin UQFN (RSE), Green (RoHS & no Sb/Br)"
U12 U13 U14 U15 U20 U44: library part CMP-0073612-3, "4-Channel ESD Protection Diode for USB Type-C and HDMI 2.0, DQA0010A (USON-10)"
U16: library part CMP-0005327-2, "1024-Kb I2C CMOS Serial EEPROM, SOIC-8"
U17: library part CMP-0067419-2, "2-Channel, 2:1 Analog Switch with Low On-State Resistance (1ohm) and Powered Off Protection, DGS0010A (VSSOP-10)"
U18: library part CMP-0073635-2, "USB Type-C Configuration Channel Logic and Port Control, RWB0012A (X2QFN-12)"
U19: library part CMP-0073678-3, "5.5V, 4A, 16mO Automotive Load Switch With Adjustable Rise Time and Optional Quick Output Discharge, DSG0008B (WSON-8)"
U21: library part CMP-0051530-2, "Single 2-Input Positive-NOR Gate, DRL0005A, LARGE T&R"
U22 U37: library part CMP-0091377-1, "1/1 Transceiver Ethernet 48-VQFN (7x7)"
U23 U50 U52 U53: library part CMP-0093539-2, "IC MUX/DEMUX DDR3 1:2 42WQFN"
U24: library part CMP-0029856-2, "Tiva C Series Microcontroller, 1024 KB Flash, 256 KB SRAM, 12 Bit, 20 Channels, -40 to 105 degC, 128-Pin TQFP (PDT), Green (RoHS & no Sb/Br), Tray"
U25 U59: library part CMP-0029369-1, "25 Mbps Dual Channels, 2 / 0, Digital Isolator, 3.3 V / 5 V, -40 to +125 degC, 8-pin SOIC (D), Green (RoHS & no Sb/Br)"
U26 U27: library part CMP-0076059-2, "High Speed, Robust EMC Dual-Channel Digital Isolator, D0008B (SOIC-8)"
U28: library part CMP-0033001-1, "Precision Micropower Shunt Voltage Reference, 0.5% accuracy, 2.5 V, 15 ppm / degC, 15 mA, -40 to 125 degC, 3-pin SOT-23 (DBZ), Green (RoHS & no Sb/Br)"
U29 U32: library part CMP-0089785-1, "3V to 17V, 3A Micro Noise (20µVRMS) and Micro Ripple (200µVPP) buck converter"
U30 U31: library part CMP-0036365-5, "Single Output LDO, 1.5A, Adj. (0.8 to 3.6V), Programmable Soft-Start, DRC0010J (VSON-10)"
U33: library part CMP-0051392-2, "Single Buffer/Driver With Open-Drain Output, DCK0005A, SMALL T&R"
U34: library part CMP-0051904-4, "Dual Schmitt-Trigger Buffer, DSF0006A, LARGE T&R"
U36: library part CMP-0067107-3, "28V, 0.5A Step-Down Converter with SNOOZE Mode, DQC0010A (WSON-10)"
U38 U39 U40 U41: library part CMP-0073613-3, "4-Channel Ultra-Low-Capacitance IEC ESD Protection Diode, DQA0010A (USON-10)"
U42: library part CMP-0079884-2, "Automotive High Speed CAN Transceiver, DRB0008J (VSON-8)"
U43: library part CMP-0074359-2, "8-Bit Bidirectional Voltage-Level Shifter with Auto Direction Sensing and +/-15-kV ESD Protect, RGY0020A (VQFN-20)"
U45: library part CMP-0036402-3, "Single Output High PSRR LDO, 1 A, Adjustable 1.2 to 5.5 V Output, 2.7 to 5.5 V Input, 8-pin SON (DRB), -40 to 125 degC, Green (RoHS & no Sb/Br)"
U46: library part CMP-0051684-3, "Single Inverter, DCK0005A, LARGE T&R"
U48: library part CMP-0044782-1, "8-Bit LED Driver with I2C Interface, D0016A, TUBE"
U49 U51 U54: library part CMP-0076540-1, "4-Bit One-of-2 FET Multiplexer/Demultiplexer 2.5-V/3.3-V Low-Voltage, High-Bandwidth Bus Switch, PW0016A (TSSOP-16)"
U55: library part CMP-0084398-1, "500-mA LDO, DRV0006A (WSON-6)"
U56 U57: library part CMP-0031336-1, "Hot-swappable, robust-EMC bidirectional I2C isolator with unidirectional clock 8-SOIC -40 to 125"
